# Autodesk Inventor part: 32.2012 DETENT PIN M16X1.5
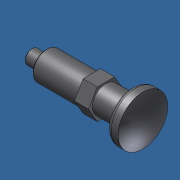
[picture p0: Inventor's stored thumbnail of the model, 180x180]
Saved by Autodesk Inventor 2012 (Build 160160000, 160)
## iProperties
Created: 2016-09
Part Number: 32.2012 DETENT PIN M16X1.5
Material: Default
Document SubType Name: Modeling
Designer: Admin
Density: 1 g/cm^3
Author: Admin
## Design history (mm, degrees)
feature "Base1"
body "Solid1"
